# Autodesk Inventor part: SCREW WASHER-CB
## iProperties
Created: 2006-07
Part Number: SCREW WASHER-CB
Material: Steel
Document SubType Name: Modeling
Designer: rollin42
Mass: 1.78877 g
Surface Area: 4.1574 cm^2
Volume: 0.227869 cm^3
Density: 7.85 g/cm^3
Stock Number: SCREW WASHER-CB
Author: rollin42
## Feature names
1. Extrusion1
2. Hole1
3. Extrusion2
